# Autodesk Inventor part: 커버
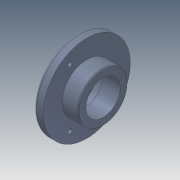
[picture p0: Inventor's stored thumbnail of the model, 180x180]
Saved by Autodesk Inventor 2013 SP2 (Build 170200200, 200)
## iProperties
Company: 한국ATC센터
Created: 2014-10
Part Number: 커버
Document SubType Name: Modeling
Designer: 한국ATC센터
Density: 2.71 g/cm^3
Material: 알루미늄-6061
Mass: 189.969 g
Surface Area: 197.235 cm^2
Volume: 70.0991 cm^3
Author: KYOUNG IL JANG
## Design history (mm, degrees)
sketch "스케치1"
  geometry: L1 (-13.5, 0)-(13.5, 0); L2 (-13.5, 0)-(-13.5, 45.5); L3 (-13.5, 45.5)-(-3.5, 45.5); L4 (-3.5, 45.5)-(-3.5, 26); L5 (-3.5, 26)-(13.5, 26); L6 (13.5, 26)-(13.5, 0); 2 further points
  constraints: 12 end point, 3 parallel, 2 perpendicular, 1 coincident, 1 horizontal, 1 midpoint
  dimensions: "d0" = 27 distance of L1.start L1.end; "d1" = 91 diameter of L3 L1; "d2" = 52 diameter of L5 L1; "d3" = 10 distance of L2.end L3.end
revolve "회전1" sketch "스케치1" stored, may be unused: angle "d4" = 90 deg
hole "구멍1" diameter "d7" = 36; stored, may be unused: countersink angle "d11" = 90 deg, drill point angle "d13" = 118 deg; dims "d5" = 10, "d6" = 10, "d8" = 6, "d9" = 40, "d10" = 8.3, "d12" = 8
sketch "스케치2"
  geometry: 2 further points
  constraints: 1 vertical alignment
  dimensions: "d14" = 35 distance of point (0, 0) point (0, 35)
hole "구멍2" sketch "스케치2" at (0, 35) diameter "d15" = 4.5; stored, may be unused: countersink angle "d19" = 90 deg, drill point angle "d21" = 118 deg; dims "d16" = 6, "d17" = 8, "d18" = 4.4, "d20" = 8
chamfer "모따기1" distance "d25" = 0.8; stored, may be unused: second distance "d26" = 2, angle "d27" = 30 deg
fillet "모깎기1" dims "d28" = 0.1, "d29" = 3
chamfer "모따기2" distance "d30" = 1; stored, may be unused: second distance "d31" = 2, angle "d32" = 30 deg
node "솔리드1"
pattern_circular "원형 패턴1" dims angle "d23" = 360 deg
